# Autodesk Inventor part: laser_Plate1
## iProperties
Shininess: 64.0
Length Units: 11269
Angle Units: 11279
Time Units: 11290
Mass Units: 11283
Length Display Precision: 3
Angle Display Precision: 2
Compacted: True
Part Number: laser_Plate1
Document SubType Name: Modeling
Created: 2004-08
Designer: John Blackburn
Manufacturer: Standard
Standards Organization: Custom
Density: 0.0
Volumn: 0.0
Area: 0.0
PropertySet Name: Model Information
Control State: 0
Master: False
Checked Out: False
Author: John Blackburn
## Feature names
1. Extrusion1
2. Hole1
3. Hole3
4. Extrusion5
5. Hole4
